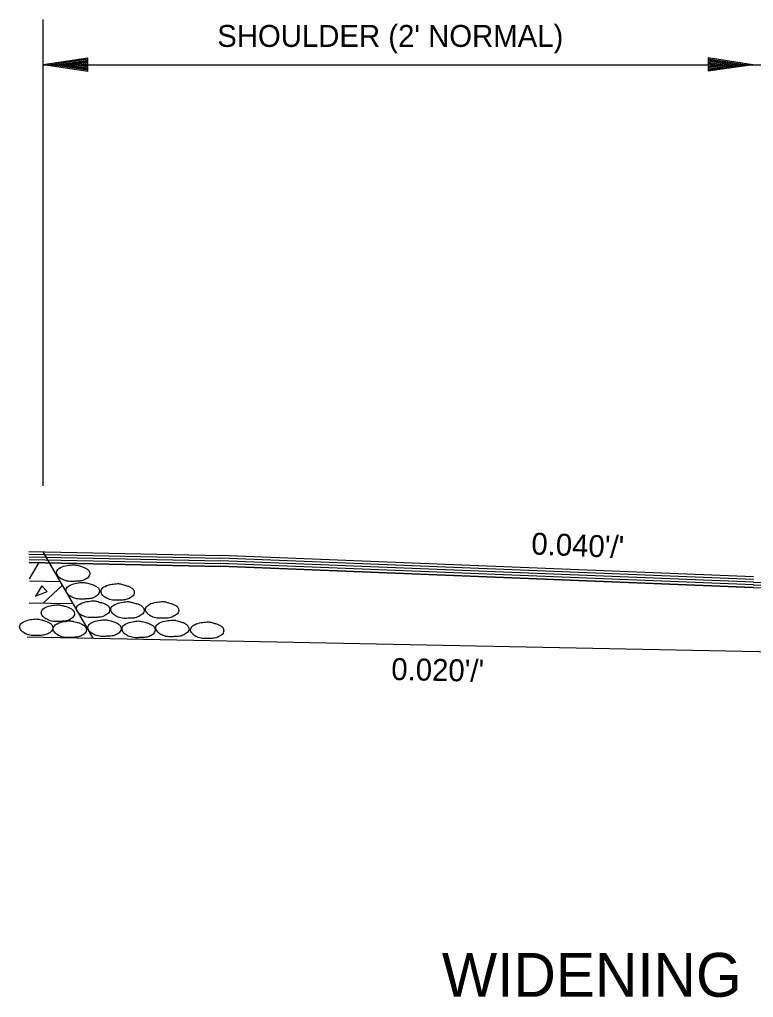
# Model space of a CAD drawing. Extents: x 1373918 to 1374069, y 381000 to 381245.
# Drawn here: x 1373961.06 to 1373981.14, y 381205.43 to 381232.17 of the extents above; entities that cross this region are included whole.
import ezdxf

# ---------------------------------------------------------------- set-up
doc = ezdxf.new("R2010")
doc.units = 0
doc.layers.add('Default', color=7, linetype='Continuous')

msp = doc.modelspace()

# ---------------------------------------------------------------- linework, layer by layer
at = {"layer": 'Default'}
for p, q in [((1373961.705, 381219.42), (1373961.705, 381232.175)), ((1373962.922, 381231.122), (1373961.705, 381230.94)), ((1373961.705, 381230.94), (1373994.349, 381230.94)), ((1373962.922, 381230.756), (1373961.705, 381230.94)), ((1373962.922, 381231.091), (1373961.909, 381230.94)), ((1373962.922, 381230.787), (1373961.909, 381230.94)), ((1373962.922, 381231.059), (1373962.118, 381230.94)), ((1373962.922, 381230.819), (1373962.118, 381230.94)), ((1373962.922, 381231.03), (1373962.322, 381230.94)), ((1373962.922, 381230.848), (1373962.322, 381230.94)), ((1373962.922, 381230.999), (1373962.526, 381230.94)), ((1373962.922, 381230.879), (1373962.526, 381230.94)), ((1373962.922, 381230.967), (1373962.73, 381230.94)), ((1373962.922, 381230.911), (1373962.73, 381230.94)), ((1373962.922, 381230.756), (1373962.922, 381231.122)), ((1373979.903, 381231.135), (1373981.12, 381230.95)), ((1373979.903, 381231.135), (1373979.903, 381230.768)), ((1373979.903, 381231.103), (1373980.916, 381230.95)), ((1373979.903, 381231.071), (1373980.707, 381230.95)), ((1373979.903, 381231.042), (1373980.503, 381230.95)), ((1373979.903, 381231.011), (1373980.299, 381230.95)), ((1373979.903, 381230.979), (1373980.095, 381230.95)), ((1373979.903, 381230.768), (1373981.12, 381230.95)), ((1373979.903, 381230.892), (1373980.299, 381230.95)), ((1373979.903, 381230.831), (1373980.707, 381230.95)), ((1373979.903, 381230.799), (1373980.916, 381230.95)), ((1373979.903, 381230.86), (1373980.503, 381230.95)), ((1373979.903, 381230.923), (1373980.095, 381230.95)), ((1373961.313, 381217.626), (1373966.565, 381217.522)), ((1373961.313, 381217.553), (1373966.565, 381217.449)), ((1373963.07, 381215.257), (1373961.705, 381217.618)), ((1373961.316, 381217.48), (1373966.565, 381217.376)), ((1373961.318, 381217.408), (1373966.565, 381217.303)), ((1373961.321, 381217.335), (1373966.56, 381217.23)), ((1373961.321, 381217.325), (1373966.565, 381217.22)), ((1373961.33, 381216.883), (1373961.593, 381217.323)), ((1373981.14, 381216.793), (1373966.56, 381217.376)), ((1373981.14, 381216.72), (1373966.56, 381217.303)), ((1373981.145, 381216.939), (1373966.565, 381217.522)), ((1373981.145, 381216.866), (1373966.565, 381217.449)), ((1373981.135, 381216.647), (1373966.555, 381217.23)), ((1373981.135, 381216.637), (1373966.565, 381217.22)), ((1373961.333, 381216.824), (1373962.174, 381216.807)), ((1373981.138, 381216.793), (1373994.437, 381216.261)), ((1373961.714, 381216.219), (1373962.231, 381216.708)), ((1373981.132, 381216.647), (1373994.432, 381216.115)), ((1373981.135, 381216.72), (1373994.434, 381216.188)), ((1373961.321, 381216.227), (1373962.523, 381216.203)), ((1373961.266, 381215.293), (1374000.118, 381214.521))]:
    msp.add_line(p, q, dxfattribs=at)
msp.add_lwpolyline([(1373961.492, 381216.403), (1373961.812, 381216.534), (1373961.667, 381216.69), (1373961.492, 381216.403)], dxfattribs=at)
for points in [[(1373962.522, 381217.266), (1373962.361, 381217.246), (1373962.177, 381217.188), (1373962.084, 381217.105), (1373962.07, 381217.047), (1373962.114, 381216.95), (1373962.167, 381216.901), (1373962.274, 381216.843), (1373962.43, 381216.809), (1373962.507, 381216.809), (1373962.629, 381216.814), (1373962.76, 381216.828), (1373962.867, 381216.872), (1373962.964, 381216.96), (1373962.979, 381217.018), (1373962.95, 381217.105), (1373962.877, 381217.164), (1373962.804, 381217.198), (1373962.697, 381217.232), (1373962.624, 381217.251), (1373962.522, 381217.266)], [(1373962.786, 381216.783), (1373962.626, 381216.764), (1373962.441, 381216.705), (1373962.344, 381216.623), (1373962.329, 381216.564), (1373962.373, 381216.467), (1373962.426, 381216.419), (1373962.533, 381216.36), (1373962.689, 381216.326), (1373962.771, 381216.326), (1373962.893, 381216.331), (1373963.024, 381216.346), (1373963.126, 381216.389), (1373963.228, 381216.477), (1373963.243, 381216.535), (1373963.214, 381216.623), (1373963.141, 381216.681), (1373963.068, 381216.715), (1373962.956, 381216.749), (1373962.888, 381216.768), (1373962.786, 381216.783)], [(1373963.74, 381216.751), (1373963.58, 381216.732), (1373963.395, 381216.674), (1373963.298, 381216.591), (1373963.283, 381216.533), (1373963.327, 381216.436), (1373963.38, 381216.387), (1373963.487, 381216.329), (1373963.643, 381216.295), (1373963.726, 381216.295), (1373963.847, 381216.299), (1373963.978, 381216.314), (1373964.08, 381216.358), (1373964.182, 381216.445), (1373964.197, 381216.504), (1373964.168, 381216.591), (1373964.095, 381216.649), (1373964.022, 381216.683), (1373963.91, 381216.717), (1373963.842, 381216.737), (1373963.74, 381216.751)], [(1373963.069, 381216.278), (1373962.908, 381216.258), (1373962.724, 381216.2), (1373962.626, 381216.117), (1373962.612, 381216.064), (1373962.656, 381215.967), (1373962.709, 381215.913), (1373962.816, 381215.855), (1373962.971, 381215.821), (1373963.054, 381215.821), (1373963.176, 381215.826), (1373963.307, 381215.84), (1373963.409, 381215.889), (1373963.511, 381215.971), (1373963.525, 381216.035), (1373963.496, 381216.122), (1373963.423, 381216.18), (1373963.35, 381216.214), (1373963.239, 381216.244), (1373963.171, 381216.268), (1373963.069, 381216.278)], [(1373964.008, 381216.256), (1373963.848, 381216.236), (1373963.663, 381216.178), (1373963.566, 381216.095), (1373963.551, 381216.042), (1373963.595, 381215.945), (1373963.649, 381215.891), (1373963.755, 381215.833), (1373963.911, 381215.799), (1373963.994, 381215.799), (1373964.115, 381215.804), (1373964.246, 381215.818), (1373964.348, 381215.867), (1373964.45, 381215.95), (1373964.465, 381216.013), (1373964.436, 381216.1), (1373964.363, 381216.159), (1373964.29, 381216.193), (1373964.178, 381216.222), (1373964.11, 381216.246), (1373964.008, 381216.256)], [(1373964.954, 381216.257), (1373964.794, 381216.238), (1373964.609, 381216.18), (1373964.517, 381216.097), (1373964.502, 381216.044), (1373964.546, 381215.946), (1373964.6, 381215.893), (1373964.706, 381215.835), (1373964.862, 381215.801), (1373964.94, 381215.801), (1373965.061, 381215.805), (1373965.192, 381215.82), (1373965.299, 381215.869), (1373965.397, 381215.951), (1373965.411, 381216.014), (1373965.382, 381216.102), (1373965.309, 381216.16), (1373965.236, 381216.194), (1373965.129, 381216.223), (1373965.056, 381216.248), (1373964.954, 381216.257)], [(1373962.104, 381216.17), (1373961.944, 381216.15), (1373961.759, 381216.092), (1373961.667, 381216.01), (1373961.652, 381215.951), (1373961.696, 381215.854), (1373961.749, 381215.805), (1373961.856, 381215.747), (1373962.012, 381215.713), (1373962.089, 381215.713), (1373962.211, 381215.718), (1373962.342, 381215.732), (1373962.449, 381215.776), (1373962.546, 381215.864), (1373962.561, 381215.922), (1373962.532, 381216.01), (1373962.459, 381216.068), (1373962.386, 381216.102), (1373962.279, 381216.136), (1373962.206, 381216.155), (1373962.104, 381216.17)], [(1373961.509, 381215.784), (1373961.348, 381215.764), (1373961.163, 381215.706), (1373961.071, 381215.623), (1373961.057, 381215.565), (1373961.1, 381215.468), (1373961.154, 381215.419), (1373961.261, 381215.361), (1373961.416, 381215.327), (1373961.494, 381215.327), (1373961.615, 381215.332), (1373961.747, 381215.346), (1373961.854, 381215.39), (1373961.951, 381215.477), (1373961.965, 381215.536), (1373961.936, 381215.623), (1373961.863, 381215.681), (1373961.79, 381215.715), (1373961.684, 381215.75), (1373961.611, 381215.769), (1373961.509, 381215.784)], [(1373962.428, 381215.731), (1373962.268, 381215.711), (1373962.083, 381215.653), (1373961.991, 381215.57), (1373961.976, 381215.512), (1373962.02, 381215.415), (1373962.073, 381215.366), (1373962.18, 381215.308), (1373962.336, 381215.274), (1373962.413, 381215.274), (1373962.535, 381215.279), (1373962.666, 381215.293), (1373962.773, 381215.337), (1373962.87, 381215.425), (1373962.885, 381215.483), (1373962.856, 381215.57), (1373962.783, 381215.629), (1373962.71, 381215.663), (1373962.603, 381215.697), (1373962.53, 381215.716), (1373962.428, 381215.731)], [(1373963.38, 381215.762), (1373963.22, 381215.743), (1373963.035, 381215.685), (1373962.943, 381215.602), (1373962.928, 381215.544), (1373962.972, 381215.447), (1373963.026, 381215.398), (1373963.133, 381215.34), (1373963.288, 381215.306), (1373963.366, 381215.306), (1373963.487, 381215.31), (1373963.619, 381215.325), (1373963.726, 381215.369), (1373963.823, 381215.456), (1373963.837, 381215.515), (1373963.808, 381215.602), (1373963.735, 381215.66), (1373963.662, 381215.694), (1373963.555, 381215.728), (1373963.483, 381215.748), (1373963.38, 381215.762)], [(1373964.309, 381215.727), (1373964.148, 381215.707), (1373963.964, 381215.649), (1373963.871, 381215.566), (1373963.857, 381215.508), (1373963.9, 381215.411), (1373963.954, 381215.362), (1373964.061, 381215.304), (1373964.216, 381215.27), (1373964.294, 381215.27), (1373964.416, 381215.275), (1373964.547, 381215.289), (1373964.654, 381215.333), (1373964.751, 381215.421), (1373964.766, 381215.479), (1373964.736, 381215.566), (1373964.664, 381215.625), (1373964.591, 381215.659), (1373964.484, 381215.693), (1373964.411, 381215.712), (1373964.309, 381215.727)], [(1373965.235, 381215.753), (1373965.074, 381215.733), (1373964.889, 381215.675), (1373964.797, 381215.592), (1373964.783, 381215.539), (1373964.826, 381215.442), (1373964.88, 381215.388), (1373964.987, 381215.33), (1373965.142, 381215.296), (1373965.22, 381215.296), (1373965.341, 381215.301), (1373965.473, 381215.315), (1373965.58, 381215.364), (1373965.677, 381215.447), (1373965.691, 381215.51), (1373965.662, 381215.597), (1373965.589, 381215.656), (1373965.516, 381215.69), (1373965.41, 381215.719), (1373965.337, 381215.743), (1373965.235, 381215.753)], [(1373966.187, 381215.703), (1373966.027, 381215.683), (1373965.842, 381215.625), (1373965.75, 381215.542), (1373965.735, 381215.489), (1373965.779, 381215.391), (1373965.832, 381215.338), (1373965.939, 381215.28), (1373966.095, 381215.246), (1373966.173, 381215.246), (1373966.294, 381215.251), (1373966.425, 381215.265), (1373966.532, 381215.314), (1373966.629, 381215.396), (1373966.644, 381215.46), (1373966.615, 381215.547), (1373966.542, 381215.605), (1373966.469, 381215.639), (1373966.362, 381215.669), (1373966.289, 381215.693), (1373966.187, 381215.703)]]:
    msp.add_spline(points, degree=3, dxfattribs=at)

# ---------------------------------------------------------------- texts
for s, height, p in [("SHOULDER (2' NORMAL)", 0.6, (1373966.466, 381231.427)), ('WIDENING FOR GUARDRAIL', 1.2, (1373972.613, 381205.449))]:
    msp.add_text(s, height=height, dxfattribs=at).set_placement(p)
for s, rotation, p in [("0.040'/'", 357.7094, (1373975.053, 381217.547)), ("0.020'/'", 358.8537, (1373971.225, 381214.115))]:
    msp.add_text(s, height=0.6, rotation=rotation, dxfattribs=at).set_placement(p)

doc.saveas('drawing.dxf')
